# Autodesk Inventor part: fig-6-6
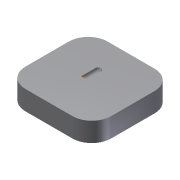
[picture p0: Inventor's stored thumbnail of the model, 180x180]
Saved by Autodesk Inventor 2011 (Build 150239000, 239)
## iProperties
Created: 2004-05
Part Number: fig-6-6
Document SubType Name: Modeling
Designer: CADCIM Technologies
Manufacturer: Standard
Standards Organization: Custom
Density: 1 g/cm^3
Author: CADCIM Technologies
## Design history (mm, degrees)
sketch "Sketch1"
  geometry: L1 (0, 0)-(44.293, 0); L2 (44.293, 0)-(44.293, 42.442); L3 (44.293, 42.442)-(0, 42.442); L4 (0, 42.442)-(0, 0)
  constraints: 8 end point, 2 parallel, 1 horizontal, 1 perpendicular
extrude "Extrusion1" new body sketch "Sketch1" distance "d0" = 10; taper "d1" = 0 deg
fillet "Fillet1" dims "d2" = 10
sketch "Sketch2"
  geometry: 1 further point
sketch "Sketch3"
  geometry: L1 (10, 42.442)-(34.293, 42.442) reference; L2 (0, 10)-(0, 32.442) reference; L3 (34.293, 0)-(10, 0) reference; L4 (44.293, 32.442)-(44.293, 10) reference; A1 r 10 centre (34.293, 32.442) between (44.293, 32.442) and (34.293, 42.442) reference; A2 r 10 centre (10, 32.442) between (10, 42.442) and (0, 32.442) reference; A3 r 10 centre (10, 10) between (0, 10) and (10, 0) reference; A4 r 10 centre (34.293, 10) between (34.293, 0) and (44.293, 10) reference; 1 further point
workpoint "Work Point1"
hole "Hole4" diameter "d33" = 3; stored, may be unused: countersink angle "d37" = 90 deg, drill point angle "d39" = 118 deg; dims "d31" = 10, "d32" = 10, "d34" = 6, "d35" = 4, "d36" = 2, "d38" = 8
body "Solid1"
